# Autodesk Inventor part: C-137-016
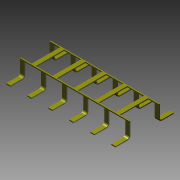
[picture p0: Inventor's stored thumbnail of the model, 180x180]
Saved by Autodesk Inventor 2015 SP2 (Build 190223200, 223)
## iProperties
Category: PARTsolutions
Company: SAMTEC
Created: 2015-08
Part Number: C-137-016
Catalog Web Link: www.cadenas.de
Description: SSM Series Terminal-SSM Series - (2,54 mm) .100" Tiger Claw™ Surface Mount Socket
Vendor: SAMTEC
Document SubType Name: Modeling
Designer: PARTuser1
Manufacturer: SAMTEC
Mass: 0.00410106 g
Surface Area: 0.851811 cm^2
Volume: 0.00410106 cm^3
Density: 1 g/cm^3
Material: Allgemein
Appearance: PSOLRGB-255-255-0
PSOL_IDENT_0: {$CADENAS_DATA\23d-libs\samtec\modelling\ssm\parts\ssm_terminal.prj},176 {VTYP=3D},{NB=C-137-016},{L
PSOL_IDENT_1: INA=C-137-016},{NN=SSM Series Terminal},{DATE=25.05.2015 11:25:09},{GEOMDATE=25.05.2015 11:24:00},{V
PSOL_IDENT_2: ERSION=},{LINEID=40},{LINESUBID=-1},{WBVAR=POS}  {NB=C-137-016},{LINA=C-137-016},{KT=DUMMY},{PN=C-13
PSOL_IDENT_3: 7-01},{ROW=-DV},{POS=6}
NN: SSM Series Terminal
NT: SSM Series - (2,54 mm) .100" Tiger Claw™ Surface Mount Socket
NB: C-137-016
NBSYN: $PN.$POS.
LINA: C-137-016
PN: C-137-01
ROW: -DV
POS: 6
SUPPLIER: SAMTEC
ARTICLENO: C-137-016
BOMINFO: C-137-016
CREATOR: CADENAS GmbH
Title: C-137-016
Author: Cadenas PARTsolutions
Comments: SSM Series - (2,54 mm) .100" Tiger Claw™ Surface Mount Socket
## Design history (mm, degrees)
sketch "Sketch_1"
  geometry: L1 (0.127, 3.518)-(0, 3.518); L2 (0, 3.518)-(0, 2.096); L3 (0.381, 1.714)-(1.778, 1.714); L4 (1.778, 1.714)-(1.778, -1.714); L5 (1.778, -1.714)-(0.381, -1.714); L6 (0, -2.096)-(0, -3.518); L7 (0, -3.518)-(0.127, -3.518); L8 (0.127, -3.518)-(0.127, -2.096); L9 (0.381, -1.842)-(1.905, -1.842); L10 (1.905, -1.842)-(1.905, 1.842); L11 (1.905, 1.842)-(0.381, 1.842); L12 (0.127, 2.096)-(0.127, 3.518); A1 r 0.381 centre (0.381, 2.095) between (0, 2.096) and (0.381, 1.714); A2 r 0.381 centre (0.381, -2.095) between (0.381, -1.714) and (0, -2.096); A3 r 0.254 centre (0.381, -2.095) between (0.381, -1.842) and (0.127, -2.096); A4 r 0.254 centre (0.381, 2.095) between (0.127, 2.096) and (0.381, 1.842)
  constraints: 24 end point, 8 point on circle, 4 centre point
extrude "Extrusion1" join sketch "Sketch_1" stored distance "d0" = 13.208; taper "d1" = 0 deg
sketch "Sketch_2"
  geometry: L1 (-7.366, 2.413)-(-7.366, 0); L2 (-7.366, 0)-(-5.334, 0); L3 (-5.334, 0)-(-5.334, 1.905); L4 (-5.334, 1.905)-(-4.826, 1.905); L5 (-4.826, 1.905)-(-4.826, 0); L6 (-4.826, 0)-(-2.794, 0); L7 (-2.794, 0)-(-2.794, 1.905); L8 (-2.794, 1.905)-(-2.286, 1.905); L9 (-2.286, 1.905)-(-2.286, 0); L10 (-2.286, 0)-(-0.254, 0); L11 (-0.254, 0)-(-0.254, 1.905); L12 (-0.254, 1.905)-(0.254, 1.905); L13 (0.254, 1.905)-(0.254, 0); L14 (0.254, 0)-(2.286, 0); L15 (2.286, 0)-(2.286, 1.905); L16 (2.286, 1.905)-(2.794, 1.905); L17 (2.794, 1.905)-(2.794, 0); L18 (2.794, 0)-(4.826, 0); L19 (4.826, 0)-(4.826, 1.905); L20 (4.826, 1.905)-(5.334, 1.905); L21 (5.334, 1.905)-(5.334, 0); L22 (5.334, 0)-(7.366, 0); L23 (7.366, 0)-(7.366, 1.905); L24 (7.366, 1.905)-(7.874, 1.905); L25 (7.874, 1.905)-(7.874, 0); L26 (7.874, 0)-(9.906, 0); L27 (9.906, 0)-(9.906, 1.905); L28 (9.906, 1.905)-(10.414, 1.905); L29 (10.414, 1.905)-(10.414, 0); L30 (10.414, 0)-(12.446, 0); L31 (12.446, 0)-(12.446, 1.905); L32 (12.446, 1.905)-(12.954, 1.905); L33 (12.954, 1.905)-(12.954, 0); L34 (12.954, 0)-(14.986, 0); L35 (14.986, 0)-(14.986, 1.905); L36 (14.986, 1.905)-(15.494, 1.905); L37 (15.494, 1.905)-(15.494, 0); L38 (15.494, 0)-(17.526, 0); L39 (17.526, 0)-(17.526, 1.905); L40 (17.526, 1.905)-(18.034, 1.905); L41 (18.034, 1.905)-(18.034, 0); L42 (18.034, 0)-(20.066, 0); L43 (20.066, 0)-(20.066, 1.905); L44 (20.066, 1.905)-(20.574, 1.905); L45 (20.574, 1.905)-(20.574, 0); L46 (20.574, 0)-(22.606, 0); L47 (22.606, 0)-(22.606, 1.905); L48 (22.606, 1.905)-(23.114, 1.905); L49 (23.114, 1.905)-(23.114, 0); L50 (23.114, 0)-(25.146, 0); L51 (25.146, 0)-(25.146, 1.905); L52 (25.146, 1.905)-(25.654, 1.905); L53 (25.654, 1.905)-(25.654, 0); L54 (25.654, 0)-(27.686, 0); L55 (27.686, 0)-(27.686, 1.905); L56 (27.686, 1.905)-(28.194, 1.905); L57 (28.194, 1.905)-(28.194, 0); L58 (28.194, 0)-(30.226, 0); L59 (30.226, 0)-(30.226, 1.905); L60 (30.226, 1.905)-(30.734, 1.905); L61 (30.734, 1.905)-(30.734, 0); L62 (30.734, 0)-(32.766, 0); L63 (32.766, 0)-(32.766, 1.905); L64 (32.766, 1.905)-(33.274, 1.905)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
  constraints: 328 end point
extrude "Extrusion2" cut sketch "Sketch_2" stored distance "d2" = 3.429; taper "d3" = 0 deg
sketch "Sketch_4"
  geometry: L1 (-6.096, -0.508)-(97.536, -0.508); L2 (97.536, -0.508)-(97.536, 1.778); L3 (97.536, 1.778)-(95.504, 1.778); L4 (95.504, 1.778)-(95.504, 0); L5 (95.504, 0)-(94.996, 0); L6 (94.996, 0)-(94.996, 1.778); L7 (94.996, 1.778)-(92.964, 1.778); L8 (92.964, 1.778)-(92.964, 0); L9 (92.964, 0)-(92.456, 0); L10 (92.456, 0)-(92.456, 1.778); L11 (92.456, 1.778)-(90.424, 1.778); L12 (90.424, 1.778)-(90.424, 0); L13 (90.424, 0)-(89.916, 0); L14 (89.916, 0)-(89.916, 1.778); L15 (89.916, 1.778)-(87.884, 1.778); L16 (87.884, 1.778)-(87.884, 0); L17 (87.884, 0)-(87.376, 0); L18 (87.376, 0)-(87.376, 1.778); L19 (87.376, 1.778)-(85.344, 1.778); L20 (85.344, 1.778)-(85.344, 0); L21 (85.344, 0)-(84.836, 0); L22 (84.836, 0)-(84.836, 1.778); L23 (84.836, 1.778)-(82.804, 1.778); L24 (82.804, 1.778)-(82.804, 0); L25 (82.804, 0)-(82.296, 0); L26 (82.296, 0)-(82.296, 1.778); L27 (82.296, 1.778)-(80.264, 1.778); L28 (80.264, 1.778)-(80.264, 0); L29 (80.264, 0)-(79.756, 0); L30 (79.756, 0)-(79.756, 1.778); L31 (79.756, 1.778)-(77.724, 1.778); L32 (77.724, 1.778)-(77.724, 0); L33 (77.724, 0)-(77.216, 0); L34 (77.216, 0)-(77.216, 1.778); L35 (77.216, 1.778)-(75.184, 1.778); L36 (75.184, 1.778)-(75.184, 0); L37 (75.184, 0)-(74.676, 0); L38 (74.676, 0)-(74.676, 1.778); L39 (74.676, 1.778)-(72.644, 1.778); L40 (72.644, 1.778)-(72.644, 0); L41 (72.644, 0)-(72.136, 0); L42 (72.136, 0)-(72.136, 1.778); L43 (72.136, 1.778)-(70.104, 1.778); L44 (70.104, 1.778)-(70.104, 0); L45 (70.104, 0)-(69.596, 0); L46 (69.596, 0)-(69.596, 1.778); L47 (69.596, 1.778)-(67.564, 1.778); L48 (67.564, 1.778)-(67.564, 0); L49 (67.564, 0)-(67.056, 0); L50 (67.056, 0)-(67.056, 1.778); L51 (67.056, 1.778)-(65.024, 1.778); L52 (65.024, 1.778)-(65.024, 0); L53 (65.024, 0)-(64.516, 0); L54 (64.516, 0)-(64.516, 1.778); L55 (64.516, 1.778)-(62.484, 1.778); L56 (62.484, 1.778)-(62.484, 0); L57 (62.484, 0)-(61.976, 0); L58 (61.976, 0)-(61.976, 1.778); L59 (61.976, 1.778)-(59.944, 1.778); L60 (59.944, 1.778)-(59.944, 0); L61 (59.944, 0)-(59.436, 0); L62 (59.436, 0)-(59.436, 1.778); L63 (59.436, 1.778)-(57.404, 1.778); L64 (57.404, 1.778)-(57.404, 0)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
  constraints: 328 end point
extrude "Extrusion3" cut sketch "Sketch_4" stored distance "d4" = 10.16; taper "d5" = 0 deg
node "terminal_XY"
node "terminal_YZ"
node "terminal_ZX"
node "terminal_X"
node "terminal_Y"
node "terminal_Z"
node "terminal_Center"
body "Solid1"
